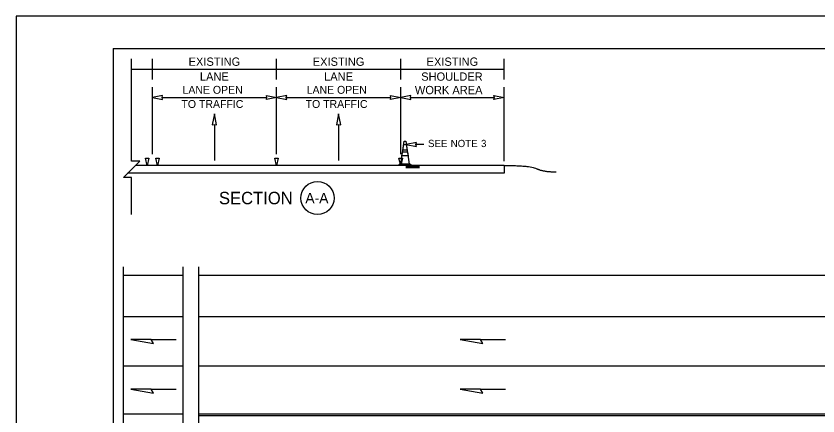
# Model space of a CAD drawing. Extents: x 99999.1 to 100096.1, y 99995 to 100010.7.
# Drawn here: x 100039.06 to 100046.81, y 100006.83 to 100010.69 of the extents above; entities that cross this region are included whole.
import ezdxf

# ---------------------------------------------------------------- set-up
doc = ezdxf.new("R2010")
doc.units = 0
for name, color, linetype in [('RD_ED_ShoulderPavedEdge', 7, 'Continuous'), ('RD_MK_LineEdgeWhite', 7, 'Continuous'), ('RD_MK_LineLane', 7, 'Continuous'), ('RD_MK_LineTwoWayLtTurn', 7, 'Continuous'), ('SH_GI_PlotLimits', 7, 'Continuous'), ('SH_GI_SheetBorder', 7, 'Continuous'), ('SH_TI_WZSectionCut', 7, 'Continuous'), ('TR_WZ_ArrowLeftStrRightTurn', 7, 'Continuous'), ('TR_WZ_TrafficConeElev', 7, 'Continuous'), ('TR_WZ_WorkZoneDetails', 7, 'Continuous'), ('TR_WZ_WorkZoneTextCurrent', 7, 'Continuous')]:
    doc.layers.add(name, color=color, linetype=linetype)

msp = doc.modelspace()

# ---------------------------------------------------------------- linework, layer by layer
at = {"layer": 'RD_ED_ShoulderPavedEdge'}
for p, q in [((100040.1016, 100008.1857), (100040.6783, 100008.1857)), ((100040.8283, 100008.1857), (100054.8933, 100008.1857))]:
    msp.add_line(p, q, dxfattribs=at)
at = {"layer": 'RD_MK_LineEdgeWhite'}
for p, q in [((100040.1016, 100007.7857), (100040.6783, 100007.7857)), ((100040.8283, 100007.7857), (100054.8933, 100007.7857))]:
    msp.add_line(p, q, dxfattribs=at)
at = {"layer": 'RD_MK_LineLane'}
for points in [[(100040.6783, 100007.3057), (100040.1016, 100007.3057)], [(100040.6783, 100007.3057), (100040.1016, 100007.3057)], [(100054.8933, 100007.3057), (100040.8283, 100007.3057)]]:
    msp.add_lwpolyline(points, dxfattribs=at)
at = {"layer": 'RD_MK_LineTwoWayLtTurn'}
for p, q in [((100040.1016, 100006.8457), (100040.6783, 100006.8457)), ((100040.8283, 100006.8457), (100054.914, 100006.8457))]:
    msp.add_line(p, q, dxfattribs=at)
msp.add_lwpolyline([(100054.8933, 100006.8257), (100040.8283, 100006.8257)], dxfattribs=at)
at = {"layer": 'SH_GI_PlotLimits'}
msp.add_lwpolyline([(100039.0625, 99999.6875), (100056.0625, 99999.6875), (100056.0625, 100010.6875), (100039.0625, 100010.6875)], close=True, dxfattribs=at)
at = {"layer": 'SH_GI_SheetBorder'}
for q in [(100040, 100000), (100055.75, 100010.375)]:
    msp.add_line((100040, 100010.375), q, dxfattribs=at)
at = {"layer": 'SH_TI_WZSectionCut'}
for p, q in [((100040.38, 100010.075), (100040.38, 100010.275)), ((100041.58, 100010.075), (100041.58, 100010.275)), ((100042.78, 100010.075), (100042.78, 100010.275)), ((100043.78, 100010.075), (100043.78, 100010.275)), ((100040.18, 100010.175), (100040.38, 100010.175)), ((100040.38, 100010.175), (100041.58, 100010.175)), ((100041.58, 100010.175), (100042.78, 100010.175)), ((100042.78, 100010.175), (100043.78, 100010.175)), ((100040.38, 100009.3547), (100040.38, 100010.001)), ((100041.58, 100009.3547), (100041.58, 100010.001)), ((100042.78, 100009.3547), (100042.78, 100010.001)), ((100043.78, 100009.2849), (100043.78, 100010.001)), ((100040.4738, 100009.901), (100041.4863, 100009.901)), ((100041.6738, 100009.901), (100042.6863, 100009.901)), ((100042.8738, 100009.901), (100043.6863, 100009.901)), ((100043.78, 100009.2449), (100040.2188, 100009.2449)), ((100042.963, 100009.2393), (100042.83, 100009.2393)), ((100042.963, 100009.2337), (100042.83, 100009.2337)), ((100042.963, 100009.228), (100042.83, 100009.228)), ((100042.963, 100009.2228), (100042.83, 100009.2228)), ((100043.78, 100009.2449), (100043.78, 100009.1699)), ((100043.78, 100009.1699), (100040.1413, 100009.1699))]:
    msp.add_line(p, q, dxfattribs=at)
for points in [[(100040.38, 100009.901), (100040.4783, 100009.8817), (100040.4738, 100009.901), (100040.4783, 100009.9203)], [(100041.58, 100009.901), (100041.4817, 100009.8817), (100041.4863, 100009.901), (100041.4817, 100009.9203)], [(100041.58, 100009.901), (100041.6783, 100009.8817), (100041.6738, 100009.901), (100041.6783, 100009.9203)], [(100042.78, 100009.901), (100042.6817, 100009.8817), (100042.6863, 100009.901), (100042.6817, 100009.9203)], [(100042.78, 100009.901), (100042.8783, 100009.8817), (100042.8738, 100009.901), (100042.8783, 100009.9203)], [(100043.78, 100009.901), (100043.6817, 100009.8817), (100043.6863, 100009.901), (100043.6817, 100009.9203)], [(100040.3133, 100009.3147), (100040.3467, 100009.3147), (100040.33, 100009.2449)], [(100040.4133, 100009.3147), (100040.4467, 100009.3147), (100040.43, 100009.2449)], [(100041.5634, 100009.3147), (100041.5967, 100009.3147), (100041.5801, 100009.2449)], [(100042.7634, 100009.3147), (100042.7967, 100009.3147), (100042.7801, 100009.2449)]]:
    msp.add_lwpolyline(points, close=True, dxfattribs=at)
msp.add_circle((100041.9766, 100008.93), 0.16, dxfattribs=at)
msp.add_open_spline([(100043.78, 100009.2449), (100044.0312, 100009.2451), (100044.1567, 100009.183), (100044.2822, 100009.1831)], degree=2, dxfattribs=at)
at = {"layer": 'TR_WZ_ArrowLeftStrRightTurn'}
for p, q in [((100040.98, 100009.6418), (100040.98, 100009.292)), ((100042.18, 100009.6418), (100042.18, 100009.292))]:
    msp.add_line(p, q, dxfattribs=at)
for points in [[(100040.98, 100009.742), (100040.9594, 100009.6369), (100040.98, 100009.6418), (100041.0006, 100009.6369)], [(100042.18, 100009.742), (100042.1594, 100009.6369), (100042.18, 100009.6418), (100042.2006, 100009.6369)]]:
    msp.add_lwpolyline(points, close=True, dxfattribs=at)
at = {"layer": 'TR_WZ_TrafficConeElev'}
for p, q in [((100042.8008, 100009.3929), (100042.8091, 100009.4471)), ((100042.8091, 100009.4471), (100042.8343, 100009.4471)), ((100042.8343, 100009.4471), (100042.8426, 100009.3929)), ((100042.7925, 100009.3388), (100042.7982, 100009.3763)), ((100042.8509, 100009.3388), (100042.7925, 100009.3388)), ((100042.7982, 100009.3763), (100042.8452, 100009.3763)), ((100042.8426, 100009.3929), (100042.8008, 100009.3929)), ((100042.8452, 100009.3763), (100042.8509, 100009.3388)), ((100042.7639, 100009.2533), (100042.7681, 100009.2575)), ((100042.7639, 100009.245), (100042.7639, 100009.2533)), ((100042.8634, 100009.2575), (100042.8753, 100009.2575)), ((100042.8753, 100009.2575), (100042.8795, 100009.2533)), ((100042.8795, 100009.2533), (100042.8795, 100009.245)), ((100042.8795, 100009.245), (100042.7639, 100009.245))]:
    msp.add_line(p, q, dxfattribs=at)
msp.add_lwpolyline([(100042.8634, 100009.2575), (100042.78, 100009.2575), (100042.8139, 100009.4783), (100042.8295, 100009.4783)], close=True, dxfattribs=at)
msp.add_lwpolyline([(100042.8634, 100009.2575), (100042.78, 100009.2575), (100042.8139, 100009.4783), (100042.8295, 100009.4783)], close=True, dxfattribs=at)
msp.add_lwpolyline([(100042.7681, 100009.2575), (100042.78, 100009.2575), (100042.8634, 100009.2575)], dxfattribs=at)
at = {"layer": 'TR_WZ_WorkZoneDetails'}
for p, q in [((100043.0043, 100009.4471), (100042.9281, 100009.4471)), ((100040.3677, 100007.565), (100040.6088, 100007.565)), ((100043.553, 100007.565), (100043.7941, 100007.565)), ((100040.3677, 100007.085), (100040.6088, 100007.085)), ((100043.553, 100007.085), (100043.7941, 100007.085))]:
    msp.add_line(p, q, dxfattribs=at)
for points in [[(100040.18, 100008.7701), (100040.18, 100009.13), (100040.1, 100009.13), (100040.2601, 100009.2849), (100040.18, 100009.2849), (100040.18, 100010.275)], [(100040.1016, 100004.9057), (100040.1016, 100006.5083), (100040.0216, 100006.5083), (100040.1817, 100006.6632), (100040.1016, 100006.6632), (100040.1016, 100008.2657)], [(100040.6783, 100004.9057), (100040.6783, 100006.5083), (100040.5983, 100006.5083), (100040.7583, 100006.6632), (100040.6783, 100006.6632), (100040.6783, 100008.2657)], [(100040.8283, 100004.9057), (100040.8283, 100006.5083), (100040.7483, 100006.5083), (100040.9083, 100006.6632), (100040.8283, 100006.6632), (100040.8283, 100008.2657)]]:
    msp.add_lwpolyline(points, dxfattribs=at)
for points in [[(100042.8343, 100009.4471), (100042.9326, 100009.4279), (100042.928, 100009.4472), (100042.9326, 100009.4664)], [(100040.1712, 100007.565), (100040.39, 100007.5264), (100040.3677, 100007.565)], [(100043.3565, 100007.565), (100043.5753, 100007.5264), (100043.553, 100007.565)], [(100040.1712, 100007.085), (100040.39, 100007.0464), (100040.3677, 100007.085)], [(100043.3565, 100007.085), (100043.5753, 100007.0464), (100043.553, 100007.085)]]:
    msp.add_lwpolyline(points, close=True, dxfattribs=at)

# ---------------------------------------------------------------- texts
at = {"layer": 'SH_TI_WZSectionCut'}
for s, height, p in [('EXISTING', 0.08, (100040.7302, 100010.207)), ('EXISTING', 0.08, (100041.9302, 100010.207)), ('EXISTING', 0.08, (100043.0302, 100010.207)), ('LANE', 0.08, (100040.8396, 100010.063)), ('LANE', 0.08, (100042.0396, 100010.063)), ('SHOULDER', 0.08, (100042.9783, 100010.063)), ('SECTION', 0.12, (100041.0235, 100008.87)), ('A-A', 0.1, (100041.8587, 100008.88))]:
    msp.add_text(s, height=height, rotation=360, dxfattribs=at).set_placement(p)
for s, height, p in [('LANE OPEN', 0.076, (100040.6714, 100009.937)), ('LANE OPEN', 0.076, (100041.8714, 100009.937)), ('WORK AREA', 0.08, (100042.9171, 100009.933)), ('TO TRAFFIC', 0.076, (100040.6613, 100009.8002)), ('TO TRAFFIC', 0.076, (100041.8613, 100009.8002))]:
    msp.add_text(s, height=height, dxfattribs=at).set_placement(p)
at = {"layer": 'TR_WZ_WorkZoneTextCurrent'}
for s, p in [('SEE', (100043.0443, 100009.4221)), ('NOTE', (100043.2635, 100009.4221)), ('3', (100043.5567, 100009.4221))]:
    msp.add_text(s, height=0.07, dxfattribs=at).set_placement(p)

doc.saveas('drawing.dxf')
